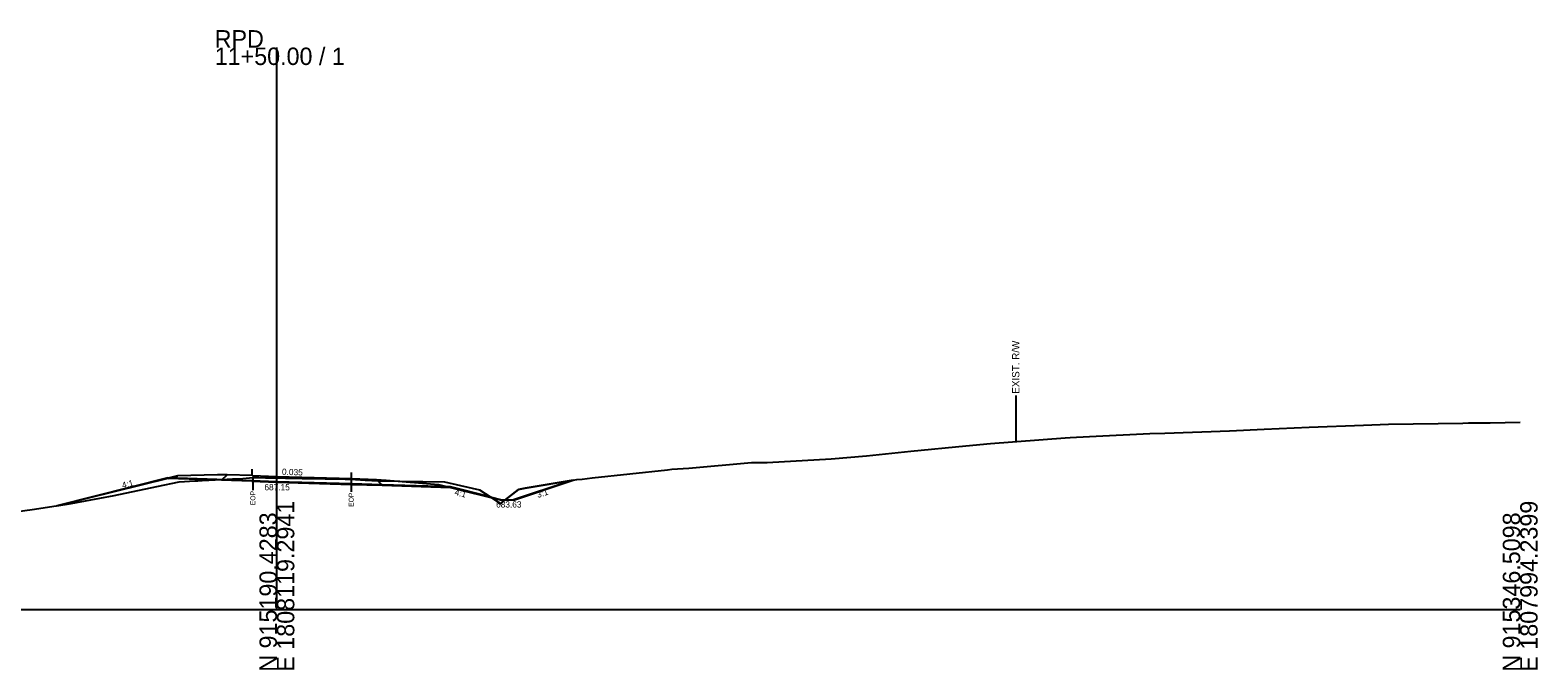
# Model space of a CAD drawing. Extents: x -26 to 403, y -10 to 8517.
# Drawn here: x 160.3 to 402.8, y 2990.3 to 3093.1 of the extents above; entities that cross this region are included whole.
import ezdxf

# ---------------------------------------------------------------- set-up
doc = ezdxf.new("R2010")
doc.units = 0
for name, color, linetype in [('Exist Cross Section Cell', 7, 'Continuous'), ('Exist XS Center Line Elevation Label', 7, 'Continuous'), ('Exist XS Ground Line', 7, 'Continuous'), ('Old_Level_10', 7, 'Continuous'), ('Prop XS Ditch Slope Text', 7, 'Continuous'), ('Prop XS Ditch Standard Text', 7, 'Continuous'), ('Prop XS Earthwork Shape', 7, 'Continuous'), ('Prop XS EOT Tick Mark', 7, 'Continuous'), ('Prop XS Finish Grade', 7, 'Continuous'), ('Prop XS Finish Grade Earthwork', 7, 'Continuous'), ('Prop XS Finish Grade Paved Shoulder', 7, 'Continuous'), ('Prop XS Finish Grade Pavement', 7, 'Continuous'), ('Prop XS Hydro Fill Slope Data', 7, 'Continuous'), ('Prop XS Pvmt Edge Slope', 7, 'Continuous'), ('Prop XS SE Text', 7, 'Continuous'), ('Prop XS Side Slope Text', 7, 'Continuous'), ('Prop XS Subgrade Earthwork', 7, 'Continuous')]:
    doc.layers.add(name, color=color, linetype=linetype)

msp = doc.modelspace()

# ---------------------------------------------------------------- linework, layer by layer
at = {"layer": 'Exist Cross Section Cell'}
for p, q in [((200, 3000), (200, 3090.31)), ((0, 3000), (200, 3000)), ((200, 3000), (400, 3000))]:
    msp.add_line(p, q, dxfattribs=at)
at = {"layer": 'Exist XS Ground Line'}
msp.add_lwpolyline([(150.89, 3014.73), (161.01, 3016.13), (166.88, 3017.03), (173.82, 3018.3), (180.67, 3019.76), (184.26, 3020.53), (186.8, 3020.67), (187.28, 3020.7), (187.97, 3020.74), (189.07, 3020.81), (191.08, 3020.92), (192.87, 3021.01), (194.51, 3021.08), (196.14, 3021.21), (197.12, 3021.19), (198.17, 3021.18), (200, 3021.15), (200.64, 3021.14), (201.36, 3021.13), (203.64, 3021.09), (204.05, 3021.08), (204.66, 3021.07), (207.78, 3021.02), (208.66, 3021), (210.97, 3020.95), (211.3, 3020.95), (211.95, 3020.94), (212.66, 3020.89), (214.18, 3020.78), (216.31, 3020.69), (219.8, 3020.61), (221.65, 3020.58), (222.75, 3020.56), (223.48, 3020.55), (226.98, 3020.5), (227.68, 3020.35), (232.6, 3019.21), (235.32, 3017.44), (235.89, 3017.01), (238.38, 3018.92), (238.85, 3019.27), (239.92, 3019.49), (248.26, 3020.89), (249.1, 3020.97), (250.71, 3021.14), (262.84, 3022.46), (263.52, 3022.54), (266.25, 3022.73), (276.33, 3023.6), (278.84, 3023.65), (289.15, 3024.21), (294.83, 3024.71), (301.96, 3025.43), (310.82, 3026.31), (314.78, 3026.67), (326.82, 3027.59), (327.59, 3027.62), (330.71, 3027.78), (340.4, 3028.27), (342.81, 3028.32), (353.22, 3028.71), (358.8, 3029.01), (366.03, 3029.3), (374.79, 3029.65), (378.84, 3029.79), (390.79, 3029.97), (391.66, 3029.98), (395.17, 3030.02), (400, 3030.1)], dxfattribs=at)
at = {"layer": 'Old_Level_10'}
for p, q in [((318.85, 3034.38), (318.85, 3026.98)), ((196.14, 3021.21), (196.14, 3019.16)), ((211.95, 3020.94), (211.95, 3018.89))]:
    msp.add_line(p, q, dxfattribs=at)
at = {"layer": 'Prop XS Earthwork Shape'}
for points in [[(164.59, 3016.68), (166.88, 3017.03), (173.82, 3018.3), (180.67, 3019.76), (184.26, 3020.53), (186.8, 3020.67), (187.28, 3020.7), (187.97, 3020.74), (189.07, 3020.81), (190.33, 3020.88), (182.46, 3021.15)], [(195.98, 3020.68), (191.11, 3020.85), (190.33, 3020.88), (191.08, 3020.92), (192.87, 3021.01), (194.51, 3021.08), (196.14, 3021.21), (197.12, 3021.19), (198.17, 3021.18), (200, 3021.15), (200.64, 3021.14), (201.36, 3021.13), (203.64, 3021.09), (204.05, 3021.08), (204.66, 3021.07), (207.78, 3021.02), (208.66, 3021), (210.97, 3020.95), (211.3, 3020.95), (211.95, 3020.94), (212.66, 3020.89), (214.18, 3020.78), (216.31, 3020.69), (219.8, 3020.61), (221.65, 3020.58), (222.75, 3020.56), (223.48, 3020.55), (226.98, 3020.5), (227.68, 3020.35), (232.6, 3019.21), (234.28, 3018.11), (227.9, 3019.7), (216.95, 3020.03), (211.98, 3020.18), (199.98, 3020.54)], [(190.33, 3020.88), (191.08, 3020.92), (192.87, 3021.01), (194.51, 3021.08), (196.14, 3021.21), (197.12, 3021.19), (198.17, 3021.18), (200, 3021.15), (200.64, 3021.14), (201.36, 3021.13), (203.64, 3021.09), (204.05, 3021.08), (204.66, 3021.07), (207.78, 3021.02), (208.66, 3021), (210.97, 3020.95), (211.3, 3020.95), (211.95, 3020.94), (212.66, 3020.89), (214.18, 3020.78), (216.31, 3020.69), (219.8, 3020.61), (221.65, 3020.58), (222.75, 3020.56), (223.48, 3020.55), (226.98, 3020.5), (227.68, 3020.35), (232.6, 3019.21), (234.28, 3018.11), (227.9, 3019.7), (216.95, 3020.03), (211.98, 3020.18), (199.98, 3020.54), (195.98, 3020.68), (191.11, 3020.85)], [(238.2, 3017.63), (247.67, 3020.79), (239.92, 3019.49), (238.85, 3019.27), (238.38, 3018.92), (236.7, 3017.63)], [(234.28, 3018.11), (236.2, 3017.63), (236.7, 3017.63), (235.89, 3017.01), (235.32, 3017.44)]]:
    msp.add_lwpolyline(points, close=True, dxfattribs=at)
at = {"layer": 'Prop XS EOT Tick Mark'}
for p, q in [((196, 3021.53), (196, 3022.53)), ((212, 3021.03), (212, 3022.03))]:
    msp.add_line(p, q, dxfattribs=at)
at = {"layer": 'Prop XS Finish Grade'}
for p, q in [((182.46, 3021.08), (184, 3021.46)), ((190.43, 3021.63), (184, 3021.46)), ((192, 3021.67), (190.43, 3021.63)), ((216, 3020.91), (217.59, 3020.78)), ((217.59, 3020.78), (226, 3020.11)), ((226, 3020.11), (227.9, 3019.63)), ((227.9, 3019.63), (227.9, 3019.63))]:
    msp.add_line(p, q, dxfattribs=at)
at = {"layer": 'Prop XS Finish Grade Earthwork'}
for p, q in [((182.46, 3021.08), (165.32, 3016.8)), ((227.9, 3019.63), (235.91, 3017.63)), ((237.92, 3017.63), (247.1, 3020.69)), ((235.91, 3017.63), (237.92, 3017.63))]:
    msp.add_line(p, q, dxfattribs=at)
at = {"layer": 'Prop XS Finish Grade Paved Shoulder'}
for p, q in [((196, 3021.53), (192, 3021.67)), ((212, 3021.03), (216, 3020.91))]:
    msp.add_line(p, q, dxfattribs=at)
at = {"layer": 'Prop XS Finish Grade Pavement'}
for p, q in [((196, 3021.53), (200, 3021.39)), ((200, 3021.39), (212, 3021.03))]:
    msp.add_line(p, q, dxfattribs=at)
at = {"layer": 'Prop XS Hydro Fill Slope Data'}
msp.add_line((184, 3021.46), (165.32, 3016.8), dxfattribs=at)
at = {"layer": 'Prop XS Pvmt Edge Slope'}
for p, q in [((192, 3021.67), (191.11, 3020.78)), ((216, 3020.91), (216.95, 3019.96))]:
    msp.add_line(p, q, dxfattribs=at)
at = {"layer": 'Prop XS Subgrade Earthwork'}
for p, q in [((191.11, 3020.78), (182.46, 3021.08)), ((195.98, 3020.61), (191.11, 3020.78)), ((195.98, 3020.61), (199.98, 3020.47)), ((199.98, 3020.47), (211.98, 3020.11)), ((211.98, 3020.11), (216.95, 3019.96)), ((216.95, 3019.96), (227.9, 3019.63))]:
    msp.add_line(p, q, dxfattribs=at)

# ---------------------------------------------------------------- texts
at = {"layer": 'Exist Cross Section Cell'}
for s, p in [('RPD', (190, 3090.31)), ('11+50.00 / 1', (190, 3087.51))]:
    msp.add_text(s, height=2.8, dxfattribs=at).set_placement(p)
for s, p in [('E 1808119.2941', (202.8, 2990)), ('E 1807994.2399', (402.8, 2990)), ('N 915190.4283', (200, 2990)), ('N 915346.5098', (400, 2990))]:
    msp.add_text(s, height=2.8, rotation=90, dxfattribs=at).set_placement(p)
at = {"layer": 'Exist XS Center Line Elevation Label'}
msp.add_text('687.15', height=1, dxfattribs=at).set_placement((197.99, 3019.15))
at = {"layer": 'Old_Level_10'}
for s, height, rotation, p in [('EXIST. R/W', 1.181, 90, (319.44, 3034.69)), ('EOP', 0.787, 90, (196.53, 3016.76)), ('EOP', 0.787, 90, (212.34, 3016.5)), ('3:1', 1, 18.4349, (241.99, 3017.91))]:
    msp.add_text(s, height=height, rotation=rotation, dxfattribs=at).set_placement(p)
at = {"layer": 'Prop XS Ditch Slope Text'}
msp.add_text('4:1', height=1, rotation=345.9638, dxfattribs=at).set_placement((228.52, 3018.42))
at = {"layer": 'Prop XS Ditch Standard Text'}
msp.add_text('683.63', height=1, dxfattribs=at).set_placement((235.26, 3016.39))
at = {"layer": 'Prop XS SE Text'}
msp.add_text('0.035', height=1, rotation=358.0123, dxfattribs=at).set_placement((200.8, 3021.65))
at = {"layer": 'Prop XS Side Slope Text'}
msp.add_text('4:1', height=1, rotation=14.0362, dxfattribs=at).set_placement((175.2, 3019.45))

doc.saveas('drawing.dxf')
